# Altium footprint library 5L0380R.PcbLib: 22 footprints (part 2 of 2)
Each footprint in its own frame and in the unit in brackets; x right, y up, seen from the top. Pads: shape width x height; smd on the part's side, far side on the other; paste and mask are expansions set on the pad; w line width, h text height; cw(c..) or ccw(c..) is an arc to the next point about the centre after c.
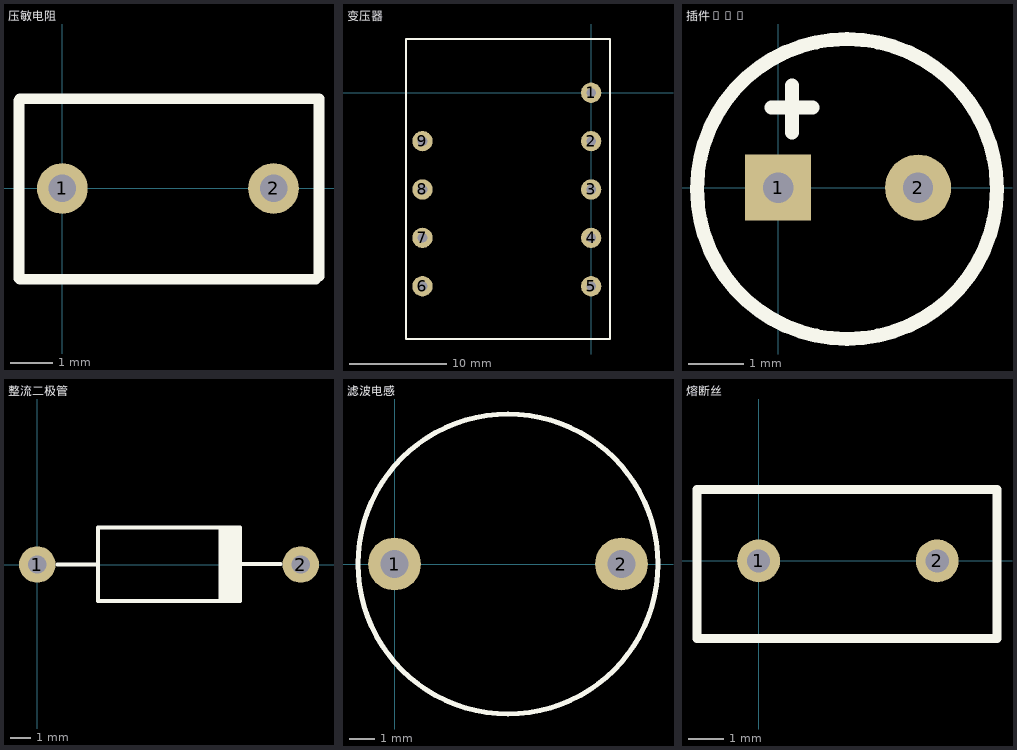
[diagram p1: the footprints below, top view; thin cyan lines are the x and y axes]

## 压敏电阻 [mm]
pads (2):
  round 1.2 hole 0.65: 1(0,0) 2(5,0)
Top Overlay:
  lines w0.254: -1.025,-2.125 -1.025,2.075 ; -1,-2.15 6,-2.15 ; -1,2.125 6,2.125 ; 6.075,-2.075 6.075,2.125

## 变压器 [mm]
pads (9):
  round 2.1 hole 1: 1(0,0) 2(0,-5) 3(0,-10) 4(0,-15) 5(0,-20) 6(-17.424,-20) 7(-17.424,-15) 8(-17.424,-10) 9(-17.424,-5)
Top Overlay:
  lines w0.2: -19.125,-25.45 -19.125,5.55 1.95,5.55 1.95,-25.45 -19.1,-25.45 -19.125,-25.45

## 插件LED [mm]
pads (2):
  rect 1.2x1.2 hole 0.55: 1(0,0)
  round 1.2 hole 0.55: 2(2.54,0)
Top Overlay:
  circle w0.254: c1.25,-0.025 r2.723
  lines w0.254: -0.125,1.45 0.625,1.45 ; 0.25,1 0.25,1.85

## 整流二极管 [mm]
pads (2):
  round 1.8 hole 0.9: 1(0,0) 2(13,0)
Top Overlay:
  rectangle: 8.95,-1.775 10,1.85
  lines w0.2: 1,0 3,0 ; 3,1.8 3,-1.8 10,-1.8 ; 3,1.825 10,1.825 10,-1.775 ; 9.8,-1.8 9.825,-1.8 ; 10,0.025 12,0.025

## 滤波电感 [mm]
pads (2):
  round 2.1 hole 1.1: 1(0,0) 2(9.017,0)
Top Overlay:
  circle w0.2: c4.508,0 r5.959

## 熔断丝 [mm]
pads (2):
  round 1.2 hole 0.65: 1(0,0) 2(5,0)
Top Overlay:
  lines w0.254: 6.675,1.975 6.675,-2.175 -1.725,-2.175 -1.725,2 6.675,2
